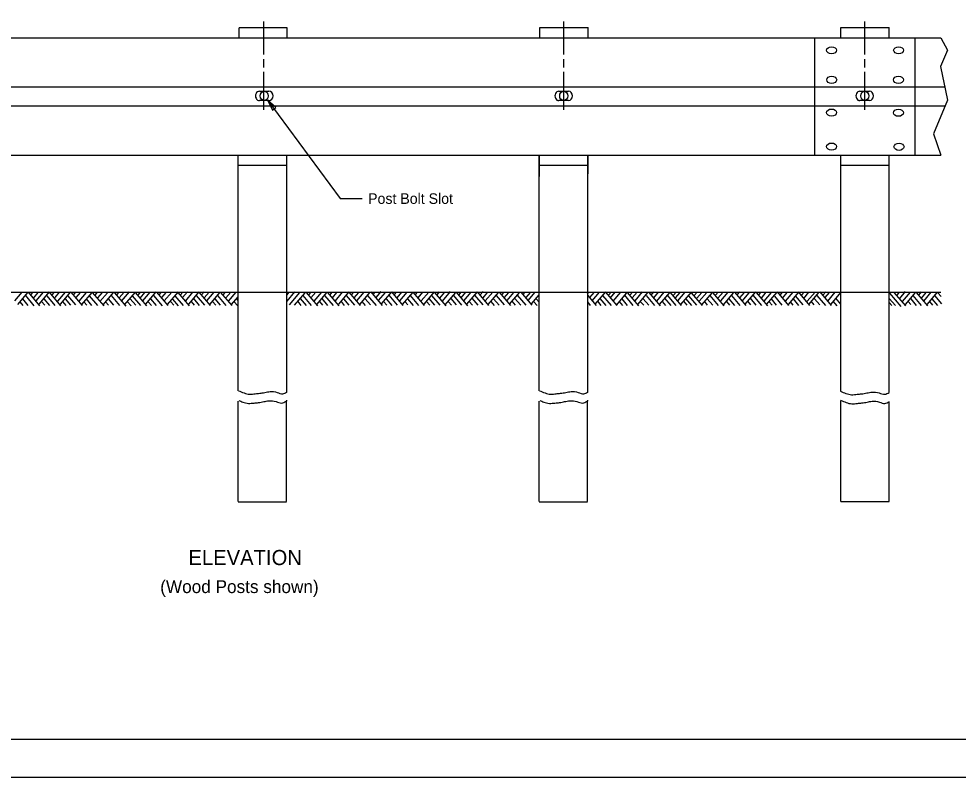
# Model space of a CAD drawing. Extents: x 0 to 34, y 0 to 22.
# Drawn here: x 10.09 to 22.52, y 0 to 10.03 of the extents above; entities that cross this region are included whole.
import ezdxf

# ---------------------------------------------------------------- set-up
doc = ezdxf.new("R2010")
doc.units = 0
for name, color, linetype in [('SH_Border', 7, 'Continuous'), ('SH_Cut_Line', 7, 'Continuous'), ('ST_Details', 7, 'Continuous'), ('ST_Text', 7, 'Continuous')]:
    doc.layers.add(name, color=color, linetype=linetype)

msp = doc.modelspace()

# ---------------------------------------------------------------- linework, layer by layer
at = {"layer": 'SH_Border'}
msp.add_lwpolyline([(1.5, 21.5), (33.5, 21.5), (33.5, 0.5), (1.5, 0.5)], close=True, dxfattribs=at)
at = {"layer": 'SH_Cut_Line'}
msp.add_lwpolyline([(0, 0), (34, 0), (34, 22), (0, 22)], close=True, dxfattribs=at)
at = {"layer": 'ST_Details'}
for p, q in [((13.333, 9.561), (13.333, 9.996)), ((17.305, 9.561), (17.305, 9.996)), ((21.289, 9.561), (21.289, 9.996)), ((13.004, 9.916), (13.641, 9.916)), ((13.004, 9.781), (13.004, 9.915)), ((13.641, 9.781), (13.641, 9.915)), ((16.988, 9.916), (17.625, 9.916)), ((16.988, 9.781), (16.988, 9.916)), ((17.625, 9.781), (17.625, 9.916)), ((20.972, 9.916), (21.61, 9.916)), ((20.972, 9.781), (20.972, 9.916)), ((21.61, 9.781), (21.61, 9.916)), ((3.808, 9.781), (22.295, 9.781)), ((20.626, 8.228), (20.626, 9.781)), ((21.957, 8.229), (21.957, 9.781)), ((22.295, 9.781), (22.383, 9.618)), ((22.383, 9.618), (22.291, 9.402)), ((13.333, 9.39), (13.333, 9.499)), ((17.305, 9.39), (17.305, 9.499)), ((21.29, 9.39), (21.29, 9.499)), ((13.333, 8.828), (13.333, 9.333)), ((17.305, 8.828), (17.305, 9.333)), ((21.29, 8.828), (21.29, 9.333)), ((22.291, 9.402), (22.383, 8.955)), ((4.021, 9.132), (22.355, 9.132)), ((13.275, 9.075), (13.338, 9.075)), ((13.338, 9.075), (13.401, 9.075)), ((17.239, 9.075), (17.302, 9.075)), ((17.302, 9.075), (17.365, 9.075)), ((21.224, 9.075), (21.287, 9.075)), ((21.287, 9.075), (21.35, 9.075)), ((22.383, 8.955), (22.199, 8.509)), ((3.99, 8.88), (22.352, 8.88)), ((13.338, 8.95), (13.275, 8.95)), ((13.401, 8.95), (13.338, 8.95)), ((17.302, 8.95), (17.239, 8.95)), ((17.365, 8.95), (17.302, 8.95)), ((21.287, 8.95), (21.224, 8.95)), ((21.35, 8.95), (21.287, 8.95)), ((22.199, 8.509), (22.295, 8.228)), ((3.808, 8.228), (22.295, 8.228)), ((12.995, 5.113), (12.995, 8.228)), ((13.636, 5.089), (13.636, 8.228)), ((16.979, 6.414), (16.979, 8.228)), ((16.979, 8.228), (16.979, 7.945)), ((17.62, 5.089), (17.62, 8.228)), ((17.62, 8.228), (17.62, 7.983)), ((20.972, 5.105), (20.972, 8.229)), ((21.61, 5.089), (21.61, 8.228)), ((12.995, 8.096), (13.636, 8.096)), ((16.979, 8.096), (17.62, 8.096)), ((20.972, 8.096), (21.61, 8.096)), ((3.808, 6.416), (22.295, 6.416)), ((9.652, 6.416), (12.995, 6.416)), ((10.037, 6.303), (10.132, 6.415)), ((10.074, 6.252), (10.215, 6.417)), ((10.293, 6.237), (10.18, 6.37)), ((10.367, 6.237), (10.217, 6.414)), ((10.252, 6.384), (10.275, 6.412)), ((10.283, 6.336), (10.351, 6.417)), ((10.32, 6.3), (10.418, 6.415)), ((10.357, 6.256), (10.496, 6.419)), ((10.57, 6.24), (10.463, 6.366)), ((10.647, 6.237), (10.497, 6.414)), ((10.532, 6.38), (10.561, 6.415)), ((10.569, 6.347), (10.627, 6.415)), ((10.606, 6.296), (10.709, 6.417)), ((10.64, 6.256), (10.779, 6.419)), ((10.844, 6.248), (10.737, 6.374)), ((10.934, 6.241), (10.783, 6.418)), ((10.818, 6.384), (10.845, 6.415)), ((10.849, 6.344), (10.911, 6.417)), ((10.886, 6.296), (10.986, 6.413)), ((10.924, 6.252), (11.061, 6.413)), ((11.133, 6.24), (11.026, 6.366)), ((11.217, 6.234), (11.066, 6.41)), ((11.098, 6.377), (11.132, 6.417)), ((11.135, 6.34), (11.196, 6.412)), ((11.163, 6.292), (11.261, 6.408)), ((11.204, 6.248), (11.347, 6.417)), ((11.425, 6.24), (11.315, 6.37)), ((11.509, 6.23), (11.359, 6.407)), ((11.387, 6.38), (11.417, 6.415)), ((11.418, 6.34), (11.482, 6.415)), ((11.449, 6.296), (11.554, 6.419)), ((11.49, 6.248), (11.633, 6.417)), ((11.704, 6.239), (11.595, 6.366)), ((11.783, 6.234), (11.633, 6.41)), ((11.667, 6.377), (11.7, 6.415)), ((11.695, 6.336), (11.762, 6.415)), ((11.732, 6.303), (11.829, 6.417)), ((11.767, 6.252), (11.908, 6.419)), ((11.992, 6.237), (11.878, 6.37)), ((12.066, 6.241), (11.916, 6.418)), ((11.947, 6.38), (11.977, 6.415)), ((11.981, 6.344), (12.042, 6.415)), ((12.015, 6.3), (12.115, 6.417)), ((12.059, 6.252), (12.202, 6.421)), ((12.27, 6.239), (12.161, 6.367)), ((12.349, 6.234), (12.199, 6.41)), ((12.227, 6.377), (12.261, 6.417)), ((12.258, 6.344), (12.322, 6.419)), ((12.298, 6.303), (12.394, 6.415)), ((12.339, 6.256), (12.478, 6.419)), ((12.55, 6.243), (12.44, 6.373)), ((12.627, 6.239), (12.477, 6.416)), ((12.507, 6.38), (12.541, 6.42)), ((12.544, 6.34), (12.607, 6.416)), ((12.577, 6.301), (12.676, 6.417)), ((12.617, 6.252), (12.756, 6.415)), ((12.832, 6.242), (12.723, 6.371)), ((12.912, 6.239), (12.761, 6.416)), ((12.794, 6.38), (12.826, 6.417)), ((12.83, 6.34), (12.894, 6.416)), ((12.863, 6.299), (12.965, 6.418)), ((12.906, 6.252), (12.992, 6.353)), ((13.635, 6.376), (13.67, 6.418)), ((13.636, 6.416), (16.979, 6.416)), ((13.64, 6.295), (13.745, 6.419)), ((13.672, 6.248), (13.811, 6.412)), ((13.739, 6.245), (13.878, 6.408)), ((13.965, 6.242), (13.853, 6.373)), ((14.046, 6.235), (13.896, 6.412)), ((13.928, 6.38), (13.96, 6.418)), ((13.956, 6.34), (14.019, 6.415)), ((14, 6.299), (14.1, 6.418)), ((14.035, 6.254), (14.173, 6.417)), ((14.253, 6.241), (14.141, 6.373)), ((14.328, 6.237), (14.177, 6.414)), ((14.21, 6.381), (14.238, 6.414)), ((14.241, 6.341), (14.301, 6.411)), ((14.28, 6.3), (14.376, 6.414)), ((14.325, 6.256), (14.464, 6.42)), ((14.536, 6.244), (14.429, 6.371)), ((14.611, 6.24), (14.461, 6.417)), ((14.494, 6.381), (14.523, 6.416)), ((14.529, 6.341), (14.589, 6.412)), ((14.563, 6.3), (14.661, 6.415)), ((14.602, 6.254), (14.741, 6.417)), ((14.822, 6.24), (14.704, 6.378)), ((14.902, 6.242), (14.752, 6.419)), ((14.78, 6.384), (14.807, 6.416)), ((14.823, 6.351), (14.884, 6.423)), ((14.852, 6.305), (14.943, 6.413)), ((14.891, 6.262), (15.026, 6.421)), ((15.102, 6.244), (14.99, 6.376)), ((15.177, 6.242), (15.027, 6.419)), ((15.064, 6.384), (15.091, 6.415)), ((15.099, 6.343), (15.16, 6.415)), ((15.131, 6.3), (15.228, 6.414)), ((15.17, 6.254), (15.309, 6.417)), ((15.384, 6.239), (15.272, 6.371)), ((15.461, 6.24), (15.311, 6.417)), ((15.341, 6.384), (15.368, 6.415)), ((15.376, 6.343), (15.438, 6.417)), ((15.417, 6.3), (15.518, 6.418)), ((15.454, 6.257), (15.593, 6.42)), ((15.667, 6.245), (15.558, 6.373)), ((15.745, 6.237), (15.594, 6.414)), ((15.625, 6.381), (15.658, 6.421)), ((15.662, 6.338), (15.728, 6.416)), ((15.697, 6.297), (15.805, 6.424)), ((15.735, 6.249), (15.874, 6.412)), ((15.952, 6.246), (15.846, 6.371)), ((16.031, 6.237), (15.881, 6.414)), ((15.918, 6.381), (15.946, 6.415)), ((15.946, 6.343), (16.008, 6.416)), ((15.978, 6.3), (16.079, 6.418)), ((16.022, 6.256), (16.16, 6.42)), ((16.236, 6.248), (16.125, 6.378)), ((16.313, 6.242), (16.163, 6.419)), ((16.194, 6.378), (16.235, 6.427)), ((16.234, 6.34), (16.295, 6.412)), ((16.264, 6.302), (16.362, 6.417)), ((16.304, 6.251), (16.443, 6.415)), ((16.519, 6.248), (16.414, 6.372)), ((16.602, 6.239), (16.451, 6.416)), ((16.482, 6.381), (16.512, 6.416)), ((16.515, 6.343), (16.575, 6.413)), ((16.555, 6.307), (16.644, 6.412)), ((16.585, 6.257), (16.721, 6.416)), ((16.807, 6.243), (16.692, 6.378)), ((16.885, 6.245), (16.74, 6.416)), ((16.763, 6.381), (16.794, 6.418)), ((16.806, 6.346), (16.867, 6.417)), ((16.831, 6.307), (16.924, 6.416)), ((16.876, 6.26), (16.977, 6.379)), ((16.979, 5.113), (16.979, 6.414)), ((17.619, 6.392), (17.637, 6.414)), ((17.62, 6.416), (20.972, 6.416)), ((17.736, 6.239), (17.62, 6.375)), ((17.65, 6.346), (17.709, 6.416)), ((17.68, 6.302), (17.778, 6.417)), ((17.72, 6.257), (17.859, 6.42)), ((17.934, 6.239), (17.822, 6.372)), ((18.012, 6.239), (17.862, 6.416)), ((17.896, 6.375), (17.93, 6.416)), ((17.921, 6.34), (17.985, 6.416)), ((17.956, 6.296), (18.057, 6.414)), ((18.001, 6.245), (18.14, 6.409)), ((18.223, 6.242), (18.111, 6.375)), ((18.298, 6.236), (18.148, 6.413)), ((18.179, 6.378), (18.212, 6.417)), ((18.209, 6.34), (18.274, 6.415)), ((18.247, 6.302), (18.347, 6.419)), ((18.282, 6.251), (18.421, 6.415)), ((18.507, 6.242), (18.397, 6.372)), ((18.585, 6.236), (18.434, 6.413)), ((18.46, 6.378), (18.496, 6.42)), ((18.496, 6.343), (18.558, 6.416)), ((18.533, 6.299), (18.634, 6.417)), ((18.571, 6.251), (18.71, 6.415)), ((18.792, 6.24), (18.678, 6.375)), ((18.863, 6.239), (18.713, 6.416)), ((18.755, 6.375), (18.789, 6.414)), ((18.784, 6.341), (18.846, 6.413)), ((18.813, 6.303), (18.909, 6.415)), ((18.854, 6.251), (18.993, 6.415)), ((19.063, 6.243), (18.957, 6.367)), ((19.14, 6.239), (18.995, 6.409)), ((19.029, 6.371), (19.068, 6.417)), ((19.064, 6.337), (19.129, 6.413)), ((19.097, 6.296), (19.196, 6.413)), ((19.132, 6.248), (19.27, 6.411)), ((19.35, 6.242), (19.24, 6.371)), ((19.428, 6.235), (19.278, 6.412)), ((19.312, 6.375), (19.348, 6.416)), ((19.344, 6.337), (19.413, 6.418)), ((19.382, 6.303), (19.479, 6.416)), ((19.417, 6.248), (19.556, 6.411)), ((19.639, 6.242), (19.529, 6.371)), ((19.717, 6.239), (19.567, 6.415)), ((19.604, 6.385), (19.634, 6.421)), ((19.636, 6.341), (19.697, 6.412)), ((19.665, 6.299), (19.758, 6.409)), ((19.706, 6.258), (19.845, 6.421)), ((19.927, 6.242), (19.812, 6.378)), ((20.003, 6.235), (19.853, 6.412)), ((19.887, 6.382), (19.916, 6.416)), ((19.919, 6.337), (19.984, 6.414)), ((19.954, 6.296), (20.053, 6.412)), ((19.989, 6.251), (20.128, 6.415)), ((20.196, 6.245), (20.095, 6.364)), ((20.283, 6.242), (20.133, 6.419)), ((20.167, 6.378), (20.199, 6.416)), ((20.199, 6.337), (20.266, 6.416)), ((20.24, 6.296), (20.341, 6.414)), ((20.278, 6.255), (20.417, 6.418)), ((20.474, 6.247), (20.372, 6.367)), ((20.56, 6.242), (20.41, 6.419)), ((20.45, 6.375), (20.485, 6.416)), ((20.479, 6.334), (20.548, 6.414)), ((20.526, 6.296), (20.629, 6.417)), ((20.547, 6.251), (20.685, 6.415)), ((20.772, 6.24), (20.658, 6.374)), ((20.846, 6.242), (20.696, 6.419)), ((20.733, 6.375), (20.771, 6.419)), ((20.762, 6.344), (20.82, 6.412)), ((20.8, 6.299), (20.898, 6.414)), ((20.838, 6.251), (20.977, 6.415)), ((21.61, 6.416), (22.295, 6.416)), ((21.771, 6.225), (21.621, 6.402)), ((21.83, 6.235), (21.679, 6.412)), ((21.717, 6.378), (21.748, 6.416)), ((21.752, 6.334), (21.829, 6.424)), ((21.787, 6.293), (21.891, 6.416)), ((21.825, 6.251), (21.963, 6.415)), ((22.04, 6.242), (21.93, 6.371)), ((22.121, 6.235), (21.971, 6.412)), ((22.002, 6.378), (22.037, 6.419)), ((22.037, 6.337), (22.104, 6.416)), ((22.07, 6.299), (22.168, 6.416)), ((22.113, 6.255), (22.252, 6.418)), ((22.31, 6.261), (22.216, 6.371)), ((22.301, 6.357), (22.257, 6.409)), ((10.145, 6.242), (10.105, 6.29)), ((10.214, 6.242), (10.142, 6.326)), ((10.432, 6.246), (10.391, 6.293)), ((10.498, 6.24), (10.426, 6.326)), ((10.715, 6.242), (10.671, 6.293)), ((10.777, 6.246), (10.709, 6.326)), ((10.99, 6.244), (10.954, 6.286)), ((11.057, 6.242), (10.985, 6.326)), ((11.276, 6.244), (11.241, 6.286)), ((11.348, 6.244), (11.275, 6.33)), ((11.575, 6.237), (11.53, 6.29)), ((11.637, 6.244), (11.564, 6.33)), ((11.844, 6.242), (11.807, 6.286)), ((11.912, 6.239), (11.838, 6.326)), ((12.141, 6.244), (12.102, 6.29)), ((12.202, 6.235), (12.127, 6.323)), ((12.413, 6.245), (12.373, 6.292)), ((12.481, 6.242), (12.405, 6.331)), ((12.695, 6.243), (12.654, 6.292)), ((12.761, 6.243), (12.688, 6.329)), ((12.982, 6.241), (12.94, 6.29)), ((12.994, 6.308), (12.975, 6.329)), ((13.829, 6.241), (13.786, 6.292)), ((13.897, 6.242), (13.819, 6.333)), ((14.115, 6.243), (14.072, 6.294)), ((14.181, 6.242), (14.105, 6.331)), ((14.402, 6.241), (14.359, 6.292)), ((14.462, 6.245), (14.392, 6.327)), ((14.677, 6.242), (14.635, 6.292)), ((14.744, 6.247), (14.674, 6.33)), ((14.962, 6.243), (14.923, 6.289)), ((15.03, 6.242), (14.955, 6.33)), ((15.24, 6.248), (15.204, 6.289)), ((15.312, 6.242), (15.237, 6.33)), ((15.529, 6.244), (15.486, 6.294)), ((15.595, 6.245), (15.521, 6.333)), ((15.815, 6.244), (15.776, 6.289)), ((15.884, 6.247), (15.811, 6.332)), ((16.093, 6.244), (16.052, 6.292)), ((16.169, 6.243), (16.09, 6.336)), ((16.385, 6.24), (16.341, 6.292)), ((16.446, 6.246), (16.374, 6.33)), ((16.665, 6.244), (16.622, 6.295)), ((16.733, 6.244), (16.652, 6.339)), ((16.95, 6.239), (16.908, 6.289)), ((16.978, 6.283), (16.938, 6.33)), ((17.658, 6.242), (17.62, 6.288)), ((17.797, 6.242), (17.752, 6.295)), ((17.864, 6.242), (17.787, 6.333)), ((18.083, 6.241), (18.04, 6.292)), ((18.149, 6.241), (18.075, 6.327)), ((18.361, 6.243), (18.321, 6.289)), ((18.431, 6.243), (18.356, 6.33)), ((18.653, 6.241), (18.61, 6.292)), ((18.724, 6.241), (18.643, 6.336)), ((18.938, 6.243), (18.893, 6.295)), ((18.997, 6.242), (18.919, 6.333)), ((19.207, 6.245), (19.164, 6.295)), ((19.276, 6.243), (19.202, 6.33)), ((19.501, 6.245), (19.462, 6.292)), ((19.568, 6.242), (19.494, 6.33)), ((19.779, 6.249), (19.739, 6.295)), ((19.851, 6.245), (19.774, 6.336)), ((20.06, 6.244), (20.022, 6.288)), ((20.121, 6.244), (20.051, 6.326)), ((20.342, 6.245), (20.305, 6.288)), ((20.416, 6.24), (20.343, 6.326)), ((20.617, 6.247), (20.576, 6.295)), ((20.693, 6.247), (20.623, 6.33)), ((20.924, 6.237), (20.871, 6.299)), ((20.972, 6.259), (20.906, 6.336)), ((21.693, 6.239), (21.612, 6.333)), ((21.644, 6.24), (21.612, 6.278)), ((21.898, 6.251), (21.863, 6.292)), ((21.973, 6.242), (21.901, 6.326)), ((22.19, 6.244), (22.149, 6.292)), ((22.253, 6.242), (22.178, 6.33)), ((13.627, 4.983), (13.642, 4.983)), ((13.632, 3.646), (13.632, 4.979)), ((17.611, 4.983), (17.626, 4.983)), ((17.616, 3.646), (17.616, 4.979)), ((20.969, 3.646), (20.969, 4.985)), ((12.995, 3.646), (12.995, 4.974)), ((16.979, 3.646), (16.979, 4.974)), ((21.61, 3.646), (21.61, 4.971)), ((12.995, 3.644), (13.632, 3.644)), ((16.979, 3.644), (17.616, 3.644)), ((20.972, 3.648), (21.61, 3.648))]:
    msp.add_line(p, q, dxfattribs=at)
for centre, major_axis, ratio in [((20.848, 9.616), (-0.0664, 0), 0.705181), ((21.736, 9.616), (-0.0664, 0), 0.705181), ((20.85, 9.225), (-0.0664, 0), 0.705181), ((21.733, 9.225), (-0.0664, 0), 0.705181), ((13.338, 9.012), (0, 0.0625), 0.850089), ((17.302, 9.012), (0, 0.0625), 0.850089), ((21.287, 9.012), (0, 0.0625), 0.850089), ((20.848, 8.792), (-0.0664, 0), 0.705181), ((21.733, 8.789), (-0.0664, 0), 0.705181), ((20.848, 8.342), (-0.0664, 0), 0.705181), ((21.741, 8.339), (-0.0664, 0), 0.705181)]:
    msp.add_ellipse(centre, major_axis=major_axis, ratio=ratio, dxfattribs=at)
for centre, start_param, end_param in [((13.275, 9.012), 0, 3.141593), ((13.401, 9.012), 3.141593, 6.283185), ((17.239, 9.012), 0, 3.141593), ((17.365, 9.012), 3.141593, 6.283185), ((21.224, 9.012), 0, 3.141593), ((21.35, 9.012), 3.141593, 6.283185)]:
    msp.add_ellipse(centre, major_axis=(0, 0.0625), ratio=0.850089, start_param=start_param, end_param=end_param, dxfattribs=at)
for points in [[(12.997, 5.113), (13.071, 5.084), (13.145, 5.066), (13.219, 5.072), (13.278, 5.078), (13.347, 5.09), (13.416, 5.101), (13.509, 5.09), (13.583, 5.072), (13.634, 5.092)], [(16.981, 5.113), (17.055, 5.084), (17.129, 5.066), (17.203, 5.072), (17.262, 5.078), (17.331, 5.09), (17.4, 5.101), (17.494, 5.09), (17.568, 5.072), (17.618, 5.092)], [(20.965, 5.106), (21.039, 5.077), (21.113, 5.06), (21.187, 5.066), (21.246, 5.071), (21.315, 5.083), (21.384, 5.095), (21.478, 5.083), (21.552, 5.066), (21.611, 5.089)], [(13.001, 4.983), (13.055, 4.962), (13.129, 4.945), (13.203, 4.95), (13.262, 4.956), (13.331, 4.968), (13.4, 4.979), (13.494, 4.968), (13.568, 4.95), (13.627, 4.974)], [(16.985, 4.983), (17.039, 4.962), (17.113, 4.945), (17.187, 4.95), (17.246, 4.956), (17.315, 4.968), (17.384, 4.979), (17.478, 4.968), (17.552, 4.95), (17.611, 4.974)], [(20.968, 4.986), (21.042, 4.957), (21.116, 4.939), (21.19, 4.945), (21.249, 4.951), (21.318, 4.962), (21.387, 4.974), (21.481, 4.962), (21.555, 4.945), (21.609, 4.966)]]:
    msp.add_spline(points, degree=3, dxfattribs=at)
at = {"layer": 'ST_Text'}
msp.add_lwpolyline([(13.384, 8.95), (14.344, 7.657), (14.635, 7.657)], dxfattribs=at)
msp.add_lwpolyline([(13.493, 8.857), (13.385, 8.95), (13.449, 8.822)], close=True, dxfattribs=at)

# ---------------------------------------------------------------- texts
for s, height, p in [('Post Bolt Slot', 0.14, (14.713, 7.584)), ('ELEVATION', 0.2, (12.335, 2.806)), ('(Wood Posts shown)', 0.17, (11.961, 2.436))]:
    msp.add_text(s, height=height, dxfattribs=at).set_placement(p)

doc.saveas('drawing.dxf')
